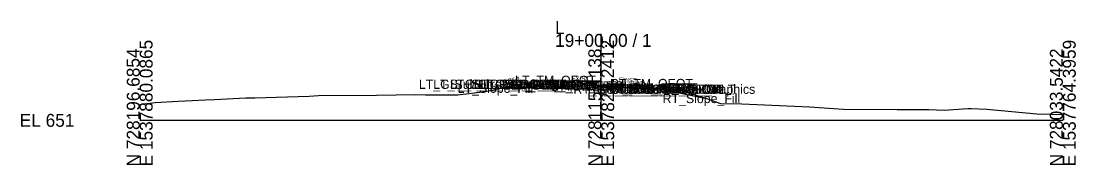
# Model space of a CAD drawing. Extents: x -26 to 1203, y -10 to 9522.
# Drawn here: x 974.3 to 1202.8, y 490.3 to 521.6 of the extents above; entities that cross this region are included whole.
import ezdxf

# ---------------------------------------------------------------- set-up
doc = ezdxf.new("R2010")
doc.units = 0
for name, color, linetype in [('Default', 7, 'Continuous'), ('Exist Cross Section Cell', 7, 'Continuous'), ('Exist XS Center Line Elevation Label', 7, 'Continuous'), ('Exist XS Ground Line', 7, 'Continuous'), ('Old_Level_63', 7, 'Continuous'), ('Prop CMT Pvmt Surface', 7, 'Continuous'), ('Prop CMT Pvmt Surface Shoulder', 7, 'Continuous'), ('Prop CMT Slope Grass', 7, 'Continuous'), ('Prop Superelevation  Arrow CELL', 7, 'Continuous'), ('Prop XS EOT Tick Mark', 7, 'Continuous'), ('Prop XS SE Text', 7, 'Continuous'), ('Prop XS Side Slope Text', 7, 'Continuous')]:
    doc.layers.add(name, color=color, linetype=linetype)

msp = doc.modelspace()

# ---------------------------------------------------------------- linework, layer by layer
at = {"layer": 'Exist Cross Section Cell'}
for p, q in [((1100, 500), (1100, 518.76)), ((1000, 500), (1100, 500)), ((1100, 500), (1200, 500))]:
    msp.add_line(p, q, dxfattribs=at)
at = {"layer": 'Exist XS Ground Line'}
msp.add_lwpolyline([(1000, 503.46), (1000.41, 503.53), (1003.33, 503.88), (1008.36, 504.17), (1011.4, 504.28), (1014.17, 504.45), (1016.22, 504.55), (1023, 504.89), (1024.94, 504.92), (1036.7, 505.28), (1038.76, 505.39), (1051.32, 505.49), (1059.8, 505.59), (1061.9, 505.57), (1068.94, 505.57), (1074.85, 506.28), (1078.36, 506.97), (1087.11, 507.43), (1087.74, 507.49), (1100, 507.21), (1100.92, 507.18), (1101.25, 507.18), (1101.56, 507.17), (1113.73, 506.66), (1115.78, 506.17), (1122.82, 504.74), (1125.82, 503.64), (1130.49, 503.55), (1145.09, 502.91), (1152.47, 502.43), (1164.11, 502.37), (1169.19, 502.36), (1170.98, 502.34), (1174.27, 502.19), (1179.4, 502.56), (1180.18, 502.55), (1183.56, 502.41), (1194.38, 501.44), (1200, 501.25)], dxfattribs=at)
at = {"layer": 'Prop CMT Pvmt Surface'}
for points in [[(1100, 507.46), (1090.4, 507.68)], [(1100, 507.46), (1111, 507)]]:
    msp.add_lwpolyline(points, dxfattribs=at)
at = {"layer": 'Prop CMT Pvmt Surface Shoulder'}
for points in [[(1090.4, 507.68), (1083.03, 507.84)], [(1111, 507), (1116.57, 506.76)]]:
    msp.add_lwpolyline(points, dxfattribs=at)
at = {"layer": 'Prop CMT Slope Grass'}
for points in [[(1083.03, 507.84), (1078.37, 506.97)], [(1083.03, 507.84), (1083.03, 507.84)], [(1116.57, 506.76), (1122.81, 504.74)], [(1116.57, 506.76), (1116.57, 506.76)]]:
    msp.add_lwpolyline(points, dxfattribs=at)
at = {"layer": 'Prop Superelevation  Arrow CELL'}
for p, q in [((1092.7, 508.24), (1098.69, 507.96)), ((1103.01, 507.78), (1109, 507.5))]:
    msp.add_line(p, q, dxfattribs=at)
for points in [[(1098.69, 507.96), (1097.22, 508.53), (1097.54, 508.02)], [(1109, 507.5), (1107.53, 508.07), (1107.85, 507.55)]]:
    msp.add_lwpolyline(points, close=True, dxfattribs=at)
at = {"layer": 'Prop XS EOT Tick Mark'}
for points in [[(1090.4, 507.68), (1090.4, 508.68)], [(1111, 507), (1111, 508)]]:
    msp.add_lwpolyline(points, dxfattribs=at)

# ---------------------------------------------------------------- texts
at = {"layer": 'Default'}
msp.add_text('-', height=0.0001, dxfattribs=at).set_placement((1000, 500))
msp.add_text('-', height=0.0001, dxfattribs=at).set_placement((1000, 500))
msp.add_text('-', height=0.0001, dxfattribs=at).set_placement((1000, 500))
at = {"layer": 'Exist Cross Section Cell'}
for s, p in [('L', (1090, 518.76)), ('19+00.00 / 1', (1090, 515.96)), ('EL 651', (974, 498.6))]:
    msp.add_text(s, height=2.8, dxfattribs=at).set_placement(p)
for s, p in [('E 1537880.0865', (1002.8, 490)), ('E 1537822.2412', (1102.8, 490)), ('E 1537764.3959', (1202.8, 490)), ('N 728196.6854', (1000, 490)), ('N 728115.1138', (1100, 490)), ('N 728033.5422', (1200, 490))]:
    msp.add_text(s, height=2.8, rotation=90, dxfattribs=at).set_placement(p)
at = {"layer": 'Exist XS Center Line Elevation Label'}
msp.add_text('658.21', height=0.75, dxfattribs=at).set_placement((1098.47, 506.21))
at = {"layer": 'Old_Level_63'}
for s, p in [('LT_TM_OEOT', (1081.34, 507.68)), ('LT_GS_OS_GR_Face_Graphics', (1060.49, 506.84)), ('LT_Sub_Trench_Out_DLT', (1063.6, 506.84)), ('LT_Sub_Trench_Out', (1067.24, 506.84)), ('LT_Slope_Fill', (1068.89, 505.97)), ('LT_GS_OS_CTL', (1072.4, 506.84)), ('LT_PS3_OEOP', (1073.27, 506.84)), ('LT_PS2_OEOP', (1073.27, 506.84)), ('LT_PS1_OEOP', (1073.84, 506.84)), ('LT_Sub_OEOT', (1080.48, 506.68)), ('LT_PV3_OEOT', (1080.57, 506.68)), ('LT_PV2_OEOT', (1080.57, 506.68)), ('LT_PV1_OEOT', (1081.14, 506.68)), ('LT_Sub_OEEOP', (1089.21, 506.46)), ('RT_PV2_OEEOP', (1089.26, 506.46)), ('RT_PV3_OEEOP', (1089.26, 506.46)), ('PV1_PGL_W', (1092.58, 506.46)), ('RT_GS_OS_GR_Face_Graphics', (1093.98, 505.76)), ('PV1_PGL', (1094.47, 506.46)), ('RT_Sub_Trench_Out_DLT', (1097.09, 505.76)), ('RT_Sub_Trench_Out', (1100.72, 505.76)), ('RT_Sub_OEOT', (1101.03, 506)), ('RT_PV2_OEOT', (1101.13, 506)), ('RT_PV3_OEOT', (1101.13, 506)), ('RT_PV1_OEOT', (1101.69, 506)), ('RT_TM_OEOT', (1101.9, 507)), ('RT_PS3_Shelf_Out', (1102.5, 505.76)), ('RT_GS_OS_CTL', (1105.89, 505.76)), ('RT_PS2_OEOP', (1106.76, 505.76)), ('RT_PS1_OEOP', (1107.32, 505.76)), ('RT_Slope_Fill', (1113.29, 503.74))]:
    msp.add_text(s, height=2, dxfattribs=at).set_placement(p)
at = {"layer": 'Prop XS SE Text'}
for rotation, p in [(358.6887, (1093.45, 508.61)), (357.6085, (1103.76, 508.3))]:
    msp.add_text('EXIST.', height=1, rotation=rotation, dxfattribs=at).set_placement(p)
at = {"layer": 'Prop XS Side Slope Text'}
for s, rotation, p in [('5.35:1', 10.592, (1078.81, 507.82)), ('3.09:1', 342.0788, (1118.23, 507.02))]:
    msp.add_text(s, height=1, rotation=rotation, dxfattribs=at).set_placement(p)

doc.saveas('drawing.dxf')
